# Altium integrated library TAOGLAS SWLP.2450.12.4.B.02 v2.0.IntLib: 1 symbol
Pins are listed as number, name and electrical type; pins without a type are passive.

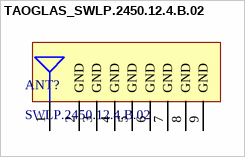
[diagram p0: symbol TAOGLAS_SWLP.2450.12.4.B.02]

## TAOGLAS_SWLP.2450.12.4.B.02
designator ANT?, comment SWLP.2450.12.4.B.02
12*12*4mm 2.4GHz Wi-Fi® SMD Patch Antenna; ComponentLibStatus: Created; MFG: Taoglas; Temp_High: +85C; Temp_Low: -40C
footprint TAOGLAS_SWLP.2450.12.4.B.02 (12*12*4mm 2.4GHz Wi-Fi® SMD Patch Antenna)
pins: 1 RF FEED, 2 GND, 3 GND, 4 GND, 5 GND, 6 GND, 7 GND, 8 GND, 9 GND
